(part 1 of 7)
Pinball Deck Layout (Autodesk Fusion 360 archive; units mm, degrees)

design "Pinball Deck Layout for Drawings" references "Pinball Flipper Full bushing"
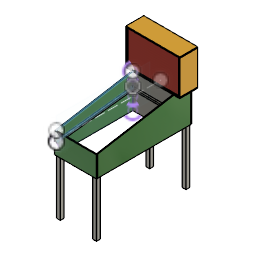
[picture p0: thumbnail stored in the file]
parameter "d345" = 2.4
sketch "Deck" plane through (0, 0, 0) normal (0, 0, 1) x axis (1, 0, 0)
  line L1 (500, 0) -> (0, 0)
  line L2 (500, 900) -> (500, 0)
  line L3 (0, 900) -> (500, 900)
  line L4 (0, 0) -> (0, 900)
  line L5 (250, 900) -> (250, 0)
  line L6 (265, 900) -> (265, 0)
  line L7 (235, 900) -> (235, 0)
  line L8 (475, 900) -> (475, 0)
  line L9 (25, 900) -> (25, 0)
  line L10 (500, 205) -> (0, 205)
  line L11 (500, 175) -> (0, 175)
  line L12 (175, 0) -> (175, 900)
  line L13 (325, 900) -> (325, 0)
  line L14 (187.7232, 167.6543) -> (175, 175)
  line L15 (189.6915, 175) -> (175, 175)
  line L16 (317.6007, 170.728) -> (325, 175)
  line L17 (333.544, 175) -> (325, 175)
  line L18 (317, 900) -> (317, 0)
  line L19 (183, 0) -> (183, 900)
  line L20 (500, 100) -> (0, 100)
  line L21 (500, 750) -> (500, 900)
  line L22 (500, 818.9103) -> (500, 750)
  line L23 (418.7386, 900) -> (350, 900)
  line L24 (0, 810) -> (500, 810)
  line L25 (0, 760) -> (500, 760)
  arc A1 centre (350, 750) radius 150 clockwise from (350, 900) to (500, 750)
  arc A2 centre (350, 750) radius 165 clockwise from (418.7386, 900) to (500, 818.7386)
  circle C1 centre (416.5624, 892.7435) radius 5
  circle C2 centre (416.5624, 892.7435) radius 2
  circle C3 centre (416.5624, 892.7435) radius 2
  circle C4 centre (416.5624, 892.7435) radius 5
  circle C5 centre (492.7435, 816.5624) radius 5
  circle C6 centre (492.7435, 816.5624) radius 2
  point P1 (0, 0)
  point P2 (0, 0)
  point P6 (0, 0)
  point P7 (250, 0)
  point P8 (250, 900)
  point P25 (175, 175)
  point P28 (325, 175)
  point P40 (350, 900)
  point P38 (350, 750)
  point P41 (350, 750)
  point P42 (500, 818.9103)
  point P43 (500, 818.7386)
  point P44 (418.7386, 900)
  coincident P1 P2
  horizontal L1
  perpendicular L1 L2
  perpendicular L2 L3
  coincident P1 P6
  perpendicular L1 L4
  midpoint L1 P7
  midpoint L3 P8
  horizontal L10
  horizontal L11
  horizontal L15
  coincident L11 P25
  coincident L12 P25
  horizontal L17
  coincident L11 P28
  coincident L13 P28
  horizontal L20
  perpendicular L3 L21
  coincident L3 P40
  coincident P38 P41
  coincident L21 P42
  coincident L2 P43
  coincident L3 P44
  tangent A1 L23
  concentric C1 C2
  concentric C3 C4
  concentric C5 C6
  dimension "d4" angle L14 L15 = 30
  dimension "d5" angle L16 L17 = 150
extrude "Extrude1" new body sketch "Deck" profile of L1 L2 L3 L4 L5 L6 L7 L8 L9 L10 L11 L12 L13 against normal blind 9
external_derived "ExternalDerived1"
move "Move1"
move "Move2"
move "Move3"
sketch "SCRATCH Sketch2" plane through (0, 0, 0) normal (0, 0, 1) x axis (1, 0, 0)
  line L1 (170.3253, 163.25) -> (183.8331, 184.2525)
  line L2 (165.6625, 180.1712) -> (177.0792, 173.7512)
  arc A1 centre (176.5753, 174.0753) radius 12.5 clockwise from (170.3253, 163.25) to (183.6642, 184.3709)
  point P2 (183.8331, 184.2525)
  point P4 (183.8331, 184.2525)
  point P3 (170.3253, 163.25)
  point P5 (170.3253, 163.25)
  point P9 (177.0792, 173.7512)
  point P10 (165.6625, 180.1712)
  coincident P2 P4
  coincident P3 P5
  midpoint L1 P9
  coincident A1 P10
move "Move4"
copy_paste_bodies "CopyPasteBodies1"
move "Move5"
move "Move6"
sketch "SCRATCH Sketch3" plane through (0, 0, 25.4) normal (0, 0, 1) x axis (-1, 0, 0)
  line L1 (-298.3283, -100.9362) -> (-297.8341, -101.7922)
  line L2 (-297.584, -100.5065) -> (-298.3283, -100.9362)
  line L3 (-297.0898, -101.3625) -> (-297.584, -100.5065)
  line L4 (-297.8341, -101.7922) -> (-297.0898, -101.3625)
  line L5 (-303.1949, -96.8044) -> (-299.6949, -102.8666)
  line L6 (-302.4506, -96.3746) -> (-303.1949, -96.8044)
  line L7 (-298.9506, -102.4368) -> (-302.4506, -96.3746)
  line L8 (-299.6949, -102.8666) -> (-298.9506, -102.4368)
  line L9 (-305.0971, -97.9026) -> (-302.5616, -102.2942)
  line L10 (-304.3528, -97.4729) -> (-305.0971, -97.9026)
  line L11 (-301.8173, -101.8644) -> (-304.3528, -97.4729)
  line L12 (-302.5616, -102.2942) -> (-301.8173, -101.8644)
  line L13 (-336.6609, -113.8819) -> (-335.4266, -116.0198)
  line L14 (-335.9166, -113.4522) -> (-336.6609, -113.8819)
  line L15 (-332.4094, -119.5268) -> (-335.9166, -113.4522)
  line L16 (-333.0876, -119.9183) -> (-332.4094, -119.5268)
  line L17 (-333.417, -119.3477) -> (-333.0876, -119.9183)
  curve K1 (-333.6687, -120.1628) -> (-333.417, -119.3477)
  curve K2 (-334.3039, -120.7529) -> (-333.6687, -120.1628)
  curve K3 (-335.4635, -121.0364) -> (-334.3039, -120.7529)
  curve K4 (-336.5842, -120.5946) -> (-335.4635, -121.0364)
  curve K5 (-337.4707, -119.5653) -> (-336.5842, -120.5946)
  curve K6 (-337.9295, -118.212) -> (-337.4707, -119.5653)
  curve K7 (-337.704, -116.9791) -> (-337.9295, -118.212)
  curve K8 (-336.9002, -116.1318) -> (-337.704, -116.9791)
  curve K9 (-336.1417, -115.9034) -> (-336.9002, -116.1318)
  curve K10 (-335.4266, -116.0198) -> (-336.1417, -115.9034)
  line L18 (-315.9189, -104.1506) -> (-314.5342, -106.549)
  line L19 (-315.1746, -103.7208) -> (-315.9189, -104.1506)
  line L20 (-312.6391, -108.1124) -> (-315.1746, -103.7208)
  line L21 (-313.309, -108.4992) -> (-312.6391, -108.1124)
  line L22 (-313.6695, -107.8747) -> (-313.309, -108.4992)
  curve K11
  curve K12 (-315.4616, -109.6841) -> (-314.6494, -109.4054)
  curve K13 (-316.176, -109.5975) -> (-315.4616, -109.6841)
  curve K14 (-316.7251, -109.1812) -> (-316.176, -109.5975)
  curve K15 (-317.1842, -108.4815) -> (-316.7251, -109.1812)
  line L23 (-318.7432, -105.7812) -> (-317.1842, -108.4815)
  line L24 (-317.9989, -105.3514) -> (-318.7432, -105.7812)
  line L25 (-316.4566, -108.0228) -> (-317.9989, -105.3514)
  curve K16 (-315.977, -108.6529) -> (-316.4566, -108.0228)
  curve K17 (-315.4612, -108.8348) -> (-315.977, -108.6529)
  curve K18 (-314.8647, -108.6695) -> (-315.4612, -108.8348)
  curve K19 (-314.2181, -107.8938) -> (-314.8647, -108.6695)
  curve K20 (-314.5342, -106.549) -> (-314.2181, -107.8938)
  line L26 (-329.0977, -111.7594) -> (-327.7106, -114.1619)
  line L27 (-328.3534, -111.3296) -> (-329.0977, -111.7594)
  line L28 (-324.8534, -117.3918) -> (-328.3534, -111.3296)
  line L29 (-325.5977, -117.8215) -> (-324.8534, -117.3918)
  line L30 (-326.8535, -115.6464) -> (-325.5977, -117.8215)
  curve K21 (-327.8199, -117.0094) -> (-326.8535, -115.6464)
  curve K22 (-328.7787, -117.3065) -> (-327.8199, -117.0094)
  curve K23 (-329.6003, -117.0724) -> (-328.7787, -117.3065)
  curve K24 (-330.3236, -116.1777) -> (-329.6003, -117.0724)
  line L31 (-331.9303, -113.3948) -> (-330.3236, -116.1777)
  line L32 (-331.186, -112.965) -> (-331.9303, -113.3948)
  line L33 (-329.5792, -115.748) -> (-331.186, -112.965)
  curve K25 (-328.8682, -116.4209) -> (-329.5792, -115.748)
  curve K26 (-328.037, -116.2801) -> (-328.8682, -116.4209)
  curve K27 (-327.5137, -115.7492) -> (-328.037, -116.2801)
  curve K28 (-327.3667, -115.044) -> (-327.5137, -115.7492)
  curve K29 (-327.7106, -114.1619) -> (-327.3667, -115.044)
  line L34 (-333.8118, -114.4811) -> (-331.2763, -118.8726)
  line L35 (-333.0675, -114.0513) -> (-333.8118, -114.4811)
  line L36 (-330.532, -118.4429) -> (-333.0675, -114.0513)
  line L37 (-331.2763, -118.8726) -> (-330.532, -118.4429)
  line L38 (-330.806, -119.6872) -> (-330.3118, -120.5432)
  line L39 (-330.0617, -119.2575) -> (-330.806, -119.6872)
  line L40 (-329.5675, -120.1135) -> (-330.0617, -119.2575)
  line L41 (-330.3118, -120.5432) -> (-329.5675, -120.1135)
  curve K30 (-325.4642, -110.9573) -> (-324.5473, -109.9096)
  curve K31 (-325.4308, -112.4762) -> (-325.4642, -110.9573)
  line L42 (-326.35, -112.7368) -> (-325.4308, -112.4762)
  curve K32 (-326.3126, -110.7055) -> (-326.35, -112.7368)
  curve K33 (-325.0098, -109.2614) -> (-326.3126, -110.7055)
  curve K34 (-323.1853, -108.7401) -> (-325.0098, -109.2614)
  curve K35 (-321.5835, -109.3563) -> (-323.1853, -108.7401)
  curve K36 (-320.3247, -110.7964) -> (-321.5835, -109.3563)
  curve K37 (-319.7328, -112.6573) -> (-320.3247, -110.7964)
  curve K38 (-320.1441, -114.3228) -> (-319.7328, -112.6573)
  curve K39 (-321.4028, -115.5375) -> (-320.1441, -114.3228)
  curve K40 (-323.2003, -115.9577) -> (-321.4028, -115.5375)
  curve K41 (-324.8166, -115.1541) -> (-323.2003, -115.9577)
  line L43 (-324.1342, -114.512) -> (-324.8166, -115.1541)
  curve K42 (-322.9659, -115.1221) -> (-324.1342, -114.512)
  curve K43 (-321.7826, -114.8415) -> (-322.9659, -115.1221)
  curve K44 (-320.8078, -113.8321) -> (-321.7826, -114.8415)
  curve K45 (-320.6675, -112.5519) -> (-320.8078, -113.8321)
  curve K46 (-321.1494, -111.278) -> (-320.6675, -112.5519)
  curve K47 (-322.1542, -110.058) -> (-321.1494, -111.278)
  curve K48 (-323.3529, -109.6005) -> (-322.1542, -110.058)
  curve K49 (-324.5473, -109.9096) -> (-323.3529, -109.6005)
  curve K50 (-310.472, -101.6619) -> (-312.3041, -101.9313)
  curve K51 (-308.9198, -103.0373) -> (-310.472, -101.6619)
  curve K52 (-308.5546, -105.236) -> (-308.9198, -103.0373)
  curve K53 (-309.6541, -106.5213) -> (-308.5546, -105.236)
  curve K54 (-311.4771, -106.7826) -> (-309.6541, -106.5213)
  curve K55 (-312.9985, -105.4749) -> (-311.4771, -106.7826)
  curve K56 (-313.5141, -103.9945) -> (-312.9985, -105.4749)
  curve K57 (-313.2096, -102.8124) -> (-313.5141, -103.9945)
  curve K58 (-312.3041, -101.9313) -> (-313.2096, -102.8124)
  curve K59 (-308.2724, -100.7779) -> (-307.6957, -100.0866)
  curve K60 (-308.1671, -101.8199) -> (-308.2724, -100.7779)
  line L44 (-308.954, -102.1473) -> (-308.1671, -101.8199)
  curve K61 (-309.0239, -100.6081) -> (-308.954, -102.1473)
  curve K62 (-308.0573, -99.4794) -> (-309.0239, -100.6081)
  curve K63 (-306.2677, -99.2318) -> (-308.0573, -99.4794)
  curve K64 (-304.7445, -100.6047) -> (-306.2677, -99.2318)
  curve K65 (-304.2616, -101.9855) -> (-304.7445, -100.6047)
  curve K66 (-304.5171, -103.1999) -> (-304.2616, -101.9855)
  curve K67 (-305.4114, -104.0718) -> (-304.5171, -103.1999)
  curve K68 (-306.7905, -104.3856) -> (-305.4114, -104.0718)
  curve K69 (-307.9669, -103.6947) -> (-306.7905, -104.3856)
  line L45 (-307.3077, -103.1652) -> (-307.9669, -103.6947)
  curve K70 (-306.5573, -103.6197) -> (-307.3077, -103.1652)
  curve K71 (-305.7937, -103.4765) -> (-306.5573, -103.6197)
  curve K72 (-305.1126, -102.5457) -> (-305.7937, -103.4765)
  curve K73 (-305.4976, -101.0671) -> (-305.1126, -102.5457)
  curve K74 (-306.5792, -99.9768) -> (-305.4976, -101.0671)
  curve K75 (-307.6957, -100.0866) -> (-306.5792, -99.9768)
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  point P165 (-326.7759, -128.0741)
  point P171 (-326.7759, -128.0741)
  point P169 (-338.2107, -105.8748)
  point P172 (-338.2107, -105.8748)
  point P173 (-332.5441, -116.6768)
  coincident P165 P171
  coincident P169 P172
  midpoint L34 P173
move "Move7"
move "Move8"
move "Move9"
sketch "Bottom Runways" plane through (0, 0, 0) normal (0, 0, 1) x axis (1, 0, 0)
  line L1 (35, 200) -> (235, 100)
  line L2 (382.2216, 133.6108) -> (309.7214, 97.3607)
  line L3 (265, 100) -> (265, 84.3827)
  line L4 (235, 75) -> (235, 100)
  line L5 (30, 177.5) -> (215, 85)
  line L6 (187.1443, 36.0721) -> (235, 60)
  line L7 (235, 60) -> (235, 75)
  line L8 (215, 70) -> (215, 85)
  line L9 (205, 45) -> (201.3653, 45.918)
  line L10 (197.2105, 61.1053) -> (215, 70)
  line L11 (95, 10) -> (170.0223, 47.5111)
  line L12 (475.0759, 10) -> (475.0759, 180)
  line L13 (500, 55) -> (500, 55)
  line L14 (500, 35) -> (500, 55)
  line L15 (500, 60) -> (500, 55)
  line L16 (465, 101) -> (475.0759, 96.9696)
  line L17 (465, 20) -> (465, 70)
  line L18 (436.9865, 55.459) -> (436.9865, 85.2054)
  line L19 (442.002, 24.3778) -> (442.002, 10)
  line L20 (437.4865, 56.1294) -> (437.4865, 75.0054)
  line L21 (442.489, 73.0044) -> (464.5, 64.2)
  line L22 (441.9865, 73.2054) -> (442.489, 73.0044)
  line L23 (464.5, 23) -> (455.75, 23)
  line L24 (455.75, 23) -> (455.75, 44.291)
  line L25 (464.5, 23) -> (464.5, 64.2)
  line L26 (437.4865, 85.0054) -> (437.4865, 75.0054)
  line L27 (441.9885, 83.2046) -> (441.9908, 73.2037)
  line L28 (382.2216, 106.6108) -> (387.2417, 104.6487)
  line L29 (437.4865, 121.6401) -> (437.4865, 85.0054)
  line L30 (441.9885, 121.6401) -> (441.9885, 83.2046)
  line L31 (437.4865, 121.6401) -> (441.9885, 121.6401)
  line L32 (436.9865, 133.2054) -> (436.9865, 112.2054)
  line L33 (436.9865, 133.2054) -> (441.4885, 133.2054)
  line L34 (442.4885, 133.2054) -> (441.4885, 133.2054)
  line L35 (442.4885, 110.0046) -> (442.4885, 133.2054)
  line L36 (442.4885, 110.0046) -> (465, 101)
  line L37 (438.1128, 99.7549) -> (441.9885, 98.2046)
  line L38 (437.4865, 100.0054) -> (438.1128, 99.7549)
  line L39 (437.4865, 75.0054) -> (441.9865, 73.2054)
  line L40 (465, 10) -> (465, 20)
  line L41 (475.0759, 180) -> (475.0152, 200)
  line L42 (265, 84.3827) -> (265, 86.0924)
  line L43 (265, 48) -> (265, 84.5)
  line L44 (265, 48) -> (265.011, 48.0055)
  line L45 (189, 10) -> (264.7, 47.85)
  line L46 (0.189, -124.2988) -> (0.189, 200)
  line L47 (500, 0) -> (500, 10)
  line L48 (189, 0) -> (264.7, 0)
  line L49 (189, 10) -> (189, 0)
  line L50 (188.3292, 10) -> (197.8101, 14.7405)
  line L51 (188.3292, 10) -> (30, 10)
  line L52 (188.3292, 0) -> (188.3292, 10)
  line L53 (30, 0) -> (188.3292, 0)
  line L54 (305, 26.7) -> (310.3, 26.7)
  line L55 (310.3, 32.3) -> (305, 32.3)
  line L56 (304.7, 32) -> (304.7, 47.85)
  line L57 (305, 0) -> (305, 10)
  line L58 (304.7, 0) -> (304.7, 10)
  line L59 (310, 27) -> (310, 32)
  line L60 (310, 32) -> (304.7, 32)
  line L61 (305, 10) -> (305, 26.7)
  line L62 (304.7, 27) -> (310, 27)
  line L63 (304.7, 10) -> (304.7, 27)
  line L64 (305, 32.3) -> (305, 48)
  line L65 (310.3, 26.7) -> (310.3, 32.3)
  line L66 (304.7076, 119.8538) -> (265, 100)
  line L67 (465, 200) -> (305.0076, 120.0038)
  line L68 (304.705, 95.4133) -> (269.0857, 81.586)
  line L69 (309.7214, 97.3607) -> (305.005, 95.5298)
  line L70 (304.7021, 67.8511) -> (265.011, 48.0055)
  line L71 (382.2216, 106.6108) -> (305.0021, 68.0011)
  line L72 (310.3, 112.3) -> (305, 112.3)
  line L73 (310, 112) -> (304.7, 112)
  line L74 (310, 107) -> (310, 112)
  line L75 (310.3, 106.7) -> (310.3, 112.3)
  line L76 (304.7, 107) -> (310, 107)
  line L77 (305, 106.7) -> (310.3, 106.7)
  line L78 (305.0062, 106.7) -> (305, 48)
  line L79 (305.0076, 120.0038) -> (305.0068, 112.3)
  line L80 (265, 48) -> (264.7, 47.85)
  line L81 (265, 0) -> (264.7, 0)
  line L82 (304.7, 10) -> (189, 10)
  line L83 (500, 10) -> (305, 10)
  line L84 (305, 0) -> (500, 0)
  line L85 (265, 0) -> (304.7, 0)
  line L86 (382.2216, 96.6108) -> (305.0021, 58.0011)
  line L87 (382.2216, 96.6108) -> (387.2417, 94.6487)
  line L88 (305.0011, 58.0005) -> (305.0021, 58.0011)
  line L89 (305.0011, 58.0005) -> (305.0021, 58.0011)
  line L90 (209, 10) -> (304.7011, 57.8505)
  line L91 (304.7062, 107) -> (304.7, 47.85)
  line L92 (304.7076, 119.8538) -> (304.7067, 112)
  line L93 (455.25, 30) -> (455.25, 23)
  line L94 (455.25, 10) -> (455.25, 23)
  line L95 (426.9865, 59.7353) -> (436.9865, 59.7353)
  line L96 (452.1681, 30) -> (455.25, 30)
  line L97 (441.9908, 56.2022) -> (441.9908, 73.2037)
  line L98 (465, 200) -> (0.189, 200)
  line L99 (30, 200) -> (35, 200)
  line L100 (30, 0) -> (30, 200)
  line L101 (470.038, 72.2189) -> (475.0759, 72.2189)
  line L102 (414.4865, 128) -> (414.4865, 95.0841)
  line L103 (414.4865, 73) -> (414.4865, 95.0841)
  line L104 (409.9865, 128) -> (409.9865, 95.0841)
  line L105 (409.9865, 73) -> (409.9865, 95.0841)
  line L106 (414.9865, 128) -> (414.9865, 120.8043)
  line L107 (414.4865, 141.8043) -> (409.9865, 141.8043)
  line L108 (414.9865, 141.8043) -> (414.4865, 141.8043)
  line L109 (414.9865, 141.8043) -> (414.9865, 128.0189)
  line L110 (409.4865, 141.8043) -> (409.4865, 128)
  line L111 (409.4865, 141.8043) -> (409.9865, 141.8043)
  line L112 (414.9865, 120.8043) -> (436.9865, 112.2054)
  line L113 (382.2216, 133.6108) -> (409.4865, 122.9541)
  line L114 (414.4865, 73) -> (409.9865, 73)
  line L115 (409.4865, 61) -> (409.4865, 95.0841)
  line L116 (414.9865, 61) -> (409.4865, 61)
  line L117 (414.9865, 61) -> (414.9865, 93.8043)
  line L118 (409.4865, 95.9541) -> (409.4865, 95.0841)
  line L119 (409.4865, 128) -> (409.4865, 122.9541)
  line L120 (414.9865, 93.8043) -> (436.9865, 85.2054)
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  point P16 (189, 10)
  point P17 (95, 10)
  point P20 (170.0223, 47.5111)
  point P23 (205, 45)
  point P28 (197.2105, 61.1053)
  point P26 (185.8525, 49.8361)
  point P27 (185.8525, 49.8361)
  point P33 (475.0759, 10)
  point P48 (441.9865, 73.2054)
  point P40 (440, 40)
  point P53 (440, 40)
  point P70 (441.9908, 73.2037)
  point P82 (437.4865, 100.0054)
  point P83 (441.9885, 98.2046)
  point P47 (442.002, 10)
  point P85 (465, 10)
  point P86 (475.0759, 72.2189)
  point P87 (475.0759, 96.9696)
  point P88 (265, 86.0924)
  point P90 (264.7, 47.85)
  point P91 (265, 84.5)
  point P30 (0.189, -124.2988)
  point P92 (0.189, -124.2988)
  point P32 (500, 0)
  point P93 (500, 0)
  point P102 (304.7, 27)
  point P114 (305.0076, 120.0038)
  point P116 (304.705, 95.4133)
  point P117 (305.005, 95.5298)
  point P118 (304.7021, 67.8511)
  point P119 (305.0021, 68.0011)
  point P128 (305.0068, 112.3)
  point P129 (305.0062, 106.7)
  point P133 (305.0011, 58.0005)
  point P134 (209, 10)
  point P135 (304.7011, 57.8505)
  point P136 (304.7062, 107)
  point P137 (304.7067, 112)
  point P138 (440, 40)
  point P140 (455.25, 10)
  point P141 (436.9865, 59.7353)
  point P193 (35, 200)
  point P195 (475.0152, 200)
  point P198 (30, 177.5)
  point P199 (30, 10)
  point P219 (409.4865, 122.9541)
  point P222 (409.4865, 95.9541)
  point P227 (409.9865, 95.7586)
  point P228 (414.4865, 93.9998)
  point P229 (409.9865, 120.7586)
  point P230 (414.4865, 118.9998)
  point P22 (185.8525, 49.8361)
  point P243 (185.8525, 49.8361)
  point P21 (185.8525, 49.8361)
  point P244 (185.8525, 49.8361)
  point P255 (40, 420)
  point P279 (40, 420)
  point P331 (290, 750)
  point P336 (290, 750)
  point P355 (290, 750)
  point P350 (290, 847)
  point P357 (290, 847)
  point P356 (290, 750)
  point P389 (103.6396, 808.3604)
  point P392 (103.6396, 808.3604)
  point P466 (437.4865, 85.0089)
  point P330 (384.1244, 660.5936)
  point P338 (381.2382, 661.4119)
  point P387 (40, 872)
  point P474 (441.9885, 96.2046)
  parallel L2 L6
  parallel L4 L7
  vertical L8
  coincident P16 L51
  coincident P17 L51
  coincident P20 L10
  coincident L6 P23
  coincident P28 L10
  coincident P26 P27
  collinear L10 L11
  coincident P33 L51
  perpendicular L12 L51
  perpendicular L17 L51
  vertical L18
  vertical L25
  coincident P48 L21
  vertical L20
  coincident P40 P53
  perpendicular L23 L25
  parallel L20 L26
  coincident L22 P70
  parallel L16 L36
  parallel L28 L120
  parallel L26 L29
  perpendicular L29 L31
  parallel L26 L32
  parallel L33 L34
  perpendicular L34 L35
  parallel L37 L38
  coincident L29 P82
  coincident L30 P83
  parallel L22 L39
  coincident P47 L51
  perpendicular L19 L51
  coincident P85 L51
  perpendicular L40 L51
  coincident L12 P86
  coincident L12 P87
  coincident L3 P88
  perpendicular L42 L51
  coincident P90 L44
  collinear L44 L45
  coincident L3 P91
  coincident P30 P92
  perpendicular L46 L51
  coincident P32 P93
  perpendicular L47 L51
  perpendicular L47 L84
  collinear L51 L82
  perpendicular L48 L52
  perpendicular L60 L64
  perpendicular L59 L60
  coincident P102 L56
  perpendicular L56 L62
  collinear L56 L63
  collinear L61 L64
  perpendicular L55 L64
  perpendicular L55 L65
  perpendicular L54 L61
  coincident P114 L66
  parallel L78 L91
  collinear L66 L67
  coincident P116 L91
  coincident P117 L78
  collinear L68 L69
  coincident P118 L91
  coincident P119 L78
  collinear L70 L71
  perpendicular L73 L74
  perpendicular L72 L75
  coincident L72 P128
  collinear L78 L79
  coincident L77 P129
  parallel L70 L80
  collinear L82 L83
  collinear L84 L85
  parallel L86 L88
  coincident L78 P133
  parallel L86 L89
  coincident L82 P134
  coincident P135 L91
  collinear L89 L90
  coincident L76 P136
  coincident L73 P137
  collinear L91 L92
  coincident P53 P138
  coincident L83 P140
  perpendicular L83 L94
  coincident L18 P141
  perpendicular L93 L96
  vertical L97
  coincident P193 L98
  collinear L98 L99
  coincident L98 P195
  perpendicular L53 L100
  coincident L100 P198
  coincident L100 P199
  perpendicular L12 L101
  parallel L107 L108
  perpendicular L108 L109
  parallel L110 L118
  perpendicular L110 L111
  collinear L112 L113
  coincident P219 L118
  perpendicular L103 L114
  parallel L105 L115
  perpendicular L115 L116
  perpendicular L116 L117
  coincident P222 L120
  collinear L118 L119
  coincident L104 P227
  coincident L103 P228
  coincident L104 P229
  coincident L102 P230
  coincident P22 P243
  coincident P21 P244
  coincident P255 P279
  coincident P331 P336
  coincident P331 P355
  coincident P350 P357
  coincident P336 P356
  coincident P389 P392
  coincident L29 P466
  dimension "d8" radius = 3
  dimension "d40" radius = 16
  dimension "d225" diameter = 7.6
  dimension "d290" diameter = 8
  dimension "d293" diameter = 15
  dimension "d363" radius = 2
  dimension "d364" radius = 1.5
  dimension "d494" diameter = 18
  dimension "d495" diameter = 4.5
  dimension "d497" diameter = 8
  dimension "d498" diameter = 8
  dimension "d499" diameter = 4.5
  dimension "d500" diameter = 4.5
  dimension "d510" diameter = 100
  dimension "d514" diameter = 8
  dimension "d515" diameter = 4.5
  dimension "d518" diameter = 8
  dimension "d519" diameter = 4.5
  dimension "d524" diameter = 8
  dimension "d525" diameter = 4.5
  dimension "d552" diameter = 18
  dimension "d553" diameter = 24
  dimension "d557" radius = 60
  dimension "d564" diameter = 8
  dimension "d565" diameter = 8
  dimension "d566" diameter = 3.8
  dimension "d567" diameter = 3.8
  dimension "d591" diameter = 8
  dimension "d592" diameter = 8
  dimension "d593" diameter = 3.8
  dimension "d594" diameter = 3.8
  dimension "d601" distance P330 P338 = 3
  dimension "d612" radius = 50
  dimension "d613" radius = 52
  dimension "d614" radius = 80
  dimension "d616" diameter = 4
  dimension "d617" diameter = 12
  dimension "d655" distance P387 P389 = 90
  dimension "d687" diameter = 8
  dimension "d688" diameter = 4.5
  dimension "d689" diameter = 8
  dimension "d690" diameter = 4.5
  dimension "d691" diameter = 8
  dimension "d692" diameter = 4.5
  dimension "d693" diameter = 8
  dimension "d694" diameter = 4.5
  dimension "d695" diameter = 8
  dimension "d696" diameter = 4.5
  dimension "d746" diameter = 8
  dimension "d747" diameter = 4.5
  dimension "d777" diameter = 4.5
  dimension "d778" diameter = 8
  dimension "d779" diameter = 12
  dimension "d780" radius = 30
  dimension "d866" radius = 10
  dimension "d888" diameter = 4.5
  dimension "d889" diameter = 8
  dimension "d890" radius = 80
  dimension "d916" diameter = 8.5
  dimension "d918" diameter = 8.5
  dimension "d924" diameter = 15
  dimension "d1303" diameter = 2.7
  dimension "d1311" distance P83 P474 = 2
sketch "Reload Plunger" plane through (0, 0, 0) normal (0, 0, 1) x axis (1, 0, 0)
  line L1 (107.246, 52.5518) -> (74.0474, 36.2161)
  line L2 (111.2277, 44.4598) -> (130.0702, 53.7314)
  line L3 (113.0223, 45.3428) -> (130.0702, 53.7314)
  line L4 (109.0487, 53.4181) -> (84.7472, 41.481)
  line L5 (111.2277, 44.4598) -> (130.0702, 53.7314)
  line L6 (74.0474, 36.2161) -> (85.5333, 12.8737)
  line L7 (130.9104, 45.2288) -> (127.3784, 52.4069)
  line L8 (116.5543, 38.1647) -> (113.0223, 45.3428)
  line L9 (130.0702, 53.7314) -> (133.6022, 46.5533)
  line L10 (128.2187, 43.9043) -> (124.6866, 51.0824)
  line L11 (116.5543, 38.1647) -> (133.6022, 46.5533)
  line L12 (130.0702, 53.7314) -> (133.6022, 46.5533)
  line L13 (118.7318, 29.2095) -> (107.246, 52.5518)
  line L14 (130.9104, 45.2288) -> (127.3784, 52.4069)
  line L15 (96.2312, 18.1378) -> (120.5273, 30.0906)
  line L16 (107.246, 52.5518) -> (74.0474, 36.2161)
  line L17 (84.7472, 41.481) -> (96.2312, 18.1378)
  line L18 (85.5333, 12.8737) -> (118.7318, 29.2095)
  line L19 (133.6022, 46.5533) -> (114.7598, 37.2817)
  line L20 (128.2187, 43.9043) -> (124.6866, 51.0824)
  line L21 (114.7598, 37.2817) -> (111.2277, 44.4598)
  line L22 (94.4613, 19.4702) -> (117.83, 30.8678)
  line L23 (108.1858, 50.6413) -> (74.9304, 34.4215)
  line L24 (108.1858, 50.6413) -> (84.8172, 39.2436)
  line L25 (108.1858, 50.6413) -> (74.9304, 34.4215)
  line L26 (108.1858, 50.6413) -> (74.9304, 34.4215)
  line L27 (85.7923, 24.6991) -> (91.2583, 27.3626)
  line L28 (108.1858, 50.6413) -> (117.83, 30.8678)
  line L29 (117.83, 30.8678) -> (84.5746, 14.6481)
  line L30 (117.83, 30.8678) -> (84.5746, 14.6481)
  line L31 (117.83, 30.8678) -> (84.5746, 14.6481)
  line L32 (110.4742, 33.3995) -> (105.2009, 30.8342)
  line L33 (105.6521, 43.2862) -> (100.3841, 40.7101)
  line L34 (88.992, 31.8227) -> (83.6843, 29.2374)
  line L35 (74.9304, 34.4215) -> (84.5746, 14.6481)
  line L36 (109.1591, 36.0958) -> (103.891, 33.5197)
  line L37 (108.1858, 50.6413) -> (117.83, 30.8678)
  line L38 (108.1858, 50.6413) -> (117.83, 30.8678)
  line L39 (74.9304, 34.4215) -> (84.5746, 14.6481)
  line L40 (106.9672, 40.5898) -> (101.6939, 38.0245)
  line L41 (92.4997, 24.6327) -> (87.1069, 22.0025)
  line L42 (74.9304, 34.4215) -> (84.5746, 14.6481)
  line L43 (87.6776, 34.5194) -> (82.2849, 31.8892)
  line L44 (85.7923, 24.6991) -> (91.1137, 27.2922)
  line L45 (84.8172, 39.2436) -> (94.4613, 19.4702)
  line L46 (92.4997, 24.6327) -> (87.1069, 22.0025)
  line L47 (117.83, 30.8678) -> (108.1858, 50.6413)
  line L48 (74.9304, 34.4215) -> (74.0474, 36.2161)
  arc A1 centre (104.4253, 32.1181) radius 1.5 clockwise from (105.2015, 30.8345) to (103.8917, 33.52)
  arc A2 centre (100.9183, 39.3084) radius 1.5 clockwise from (101.6945, 38.0249) to (100.3847, 40.7103)
  arc A3 centre (109.818, 34.7483) radius 1.5 clockwise from (109.1591, 36.0958) to (110.4742, 33.3995)
  arc A4 centre (82.9424, 30.541) radius 1.5 clockwise from (83.6843, 29.2374) to (82.2849, 31.8892)
  circle C1 centre (103.6147, 40.6236) radius 1.5
  arc A5 centre (91.8421, 25.9809) radius 1.5 clockwise from (91.2583, 27.3626) to (92.4997, 24.6327)
  circle C2 centre (103.6147, 40.6236) radius 1.5
  arc A6 centre (106.3111, 41.9387) radius 1.5 clockwise from (105.6521, 43.2862) to (106.9672, 40.5898)
  circle C3 centre (111.1442, 33.1699) radius 2
  circle C4 centre (107.1216, 33.4332) radius 1.5
  arc A7 centre (100.9183, 39.3084) radius 1.5 clockwise from (101.6945, 38.0249) to (100.3847, 40.7103)
  arc A8 centre (86.4494, 23.3507) radius 1.5 clockwise from (87.1069, 22.0025) to (85.7923, 24.6991)
  arc A9 centre (82.9424, 30.541) radius 1.5 clockwise from (83.6845, 29.2374) to (82.2849, 31.8892)
  arc A10 centre (91.8421, 25.9809) radius 1.5 clockwise from (91.1137, 27.2922) to (92.4997, 24.6327)
  arc A11 centre (86.4494, 23.3507) radius 1.5 clockwise from (87.1069, 22.0025) to (85.7923, 24.6991)
  arc A12 centre (86.4494, 23.3507) radius 1.5 clockwise from (87.1069, 22.0025) to (85.7923, 24.6991)
  circle C5 centre (107.1216, 33.4332) radius 1.5
  circle C6 centre (89.1458, 24.6658) radius 1.5
  arc A13 centre (104.4253, 32.1181) radius 1.5 clockwise from (105.2015, 30.8345) to (103.8917, 33.52)
  circle C7 centre (91.9524, 37.1607) radius 2
  arc A14 centre (88.3352, 33.1712) radius 1.5 clockwise from (87.6776, 34.5194) to (88.992, 31.8227)
  circle C8 centre (89.1458, 24.6658) radius 1.5
  circle C9 centre (89.1458, 24.6658) radius 1.5
  arc A15 centre (82.9424, 30.541) radius 1.5 clockwise from (83.6845, 29.2374) to (82.2849, 31.8892)
  circle C10 centre (85.6388, 31.8561) radius 1.5
  circle C11 centre (107.1216, 33.4332) radius 1.5
  arc A16 centre (104.4253, 32.1181) radius 1.5 clockwise from (105.2009, 30.8342) to (103.891, 33.5197)
  circle C12 centre (103.6147, 40.6236) radius 1.5
  circle C13 centre (85.6388, 31.8561) radius 1.5
  arc A17 centre (100.9183, 39.3084) radius 1.5 clockwise from (101.6939, 38.0245) to (100.3841, 40.7101)
  circle C14 centre (85.6388, 31.8561) radius 1.5
  circle C15 centre (111.1442, 33.1699) radius 3.25
  circle C16 centre (107.1216, 33.4332) radius 3.25
  circle C17 centre (103.6147, 40.6236) radius 3.25
  circle C18 centre (91.9524, 37.1607) radius 3.25
  circle C19 centre (89.1458, 24.6658) radius 3.25
  circle C20 centre (85.6388, 31.8561) radius 3.25
  point P11 (133.6022, 46.5533)
  point P33 (133.6022, 46.5533)
  point P12 (130.0702, 53.7314)
  point P28 (130.0702, 53.7314)
  point P30 (133.6022, 46.5533)
  point P3 (127.3784, 52.4069)
  point P15 (127.3784, 52.4069)
  point P2 (130.9104, 45.2288)
  point P10 (130.9104, 45.2288)
  point P29 (124.6866, 51.0824)
  point P35 (124.6866, 51.0824)
  point P34 (128.2187, 43.9043)
  point P36 (128.2187, 43.9043)
  point P27 (84.7472, 41.481)
  point P40 (94.4613, 19.4702)
  point P41 (94.4613, 19.4702)
  point P45 (94.4613, 19.4702)
  point P22 (74.0474, 36.2161)
  point P136 (74.9304, 34.4215)
  coincident P11 P33
  coincident P12 P28
  perpendicular L3 L12
  perpendicular L5 L8
  coincident P30 P33
  perpendicular L8 L11
  coincident P3 P15
  coincident P2 P10
  coincident P29 P35
  coincident P34 P36
  coincident P27 L16
  perpendicular L15 L17
  coincident P40 P41
  perpendicular L24 L45
  perpendicular L24 L47
  coincident P41 P45
  perpendicular L22 L45
  perpendicular L1 L48
  concentric C3 C15
  dimension "d9" distance P22 P136 = 2
  dimension "d925" diameter C3 = 4
  dimension "d926" diameter C7 = 4
sketch "Reload Flipper" plane through (0, 0, 0) normal (0, 0, 1) x axis (1, 0, 0)
  line L1 (189.2611, 51.9302) -> (189.2253, 51.9883)
  line L2 (182.2905, 34.7509) -> (182.74, 19.3347)
  line L3 (184.5475, 75.9042) -> (188.377, 65.1291)
  line L4 (190.2871, 34.984) -> (190.8175, 16.7929)
  line L5 (193.9662, 36.6294) -> (185.8525, 49.8361)
  line L6 (190.2939, 34.7513) -> (190.1715, 34.95)
  line L7 (170.4136, 70.881) -> (174.243, 60.106)
  circle C1 centre (185.8525, 49.8361) radius 12.5
  arc A1 centre (185.7387, 19.4222) radius 3 clockwise from (185.7275, 16.4222) to (182.74, 19.3347)
  arc A2 centre (185.8525, 49.8361) radius 33.4141 clockwise from (190.8175, 16.7929) to (185.7275, 16.4222)
  circle C2 centre (185.8525, 49.8361) radius 5.375
  arc A3 centre (185.8525, 49.8361) radius 15.5 clockwise from (182.2905, 34.7509) to (174.1149, 59.9593)
  circle C3 centre (177.4806, 73.3926) radius 1.85
  arc A4 centre (177.4806, 73.3926) radius 7.5 clockwise from (170.4136, 70.881) to (184.5475, 75.9042)
  arc A5 centre (185.8525, 49.8361) radius 15.5 clockwise from (197.0999, 39.1709) to (190.1715, 34.95)
  arc A6 centre (185.8525, 49.8361) radius 15.5 clockwise from (174.1149, 59.9593) to (174.243, 60.106)
  arc A7 centre (185.8525, 49.8361) radius 15.5 clockwise from (188.377, 65.1291) to (197.0999, 39.1709)
  point P9 (197.0999, 39.1709)
  point P12 (174.1149, 59.9593)
  point P8 (185.8525, 49.8361)
  point P20 (185.8525, 49.8361)
  point P2 (185.8525, 49.8361)
  point P26 (185.8525, 49.8361)
  point P25 (185.8525, 49.8361)
  point P3 (190.2871, 34.984)
  point P23 (190.2939, 34.7513)
  point P31 (193.9662, 36.6294)
  point P22 (185.8525, 49.8361)
  point P27 (185.8525, 49.8361)
  concentric C2 A7
  coincident P9 L1
  coincident P12 A7
  concentric A3 A7
  concentric C3 A4
  coincident P8 P20
  concentric C1 C2
  coincident P2 P26
  coincident P2 P25
  coincident P3 A5
  coincident P23 L4
  coincident P31 A5
  tangent A1 L2
  tangent A1 A2
  coincident P22 P27
  dimension "d365" diameter C2 = 10.75
  dimension "d366" diameter A7 = 31
  dimension "d367" diameter C3 = 3.7
  dimension "d368" diameter A4 = 15
  dimension "d369" diameter C1 = 25
  dimension "d370" radius A1 = 3
sketch "reload coupling" plane through (0, 0, 0) normal (0, 0, 1) x axis (1, 0, 0)
  line L1 (182.9196, 67.3244) -> (131.992, 42.4436)
  line L2 (177.176, 81.1418) -> (125.3353, 55.9165)
  line L3 (123.51, 50.5264) -> (126.6606, 44.2444)
  line L4 (134.7248, 43.7787) -> (128.4353, 40.7059)
  line L5 (168.7441, 60.399) -> (165.2756, 67.4985)
  line L6 (162.1861, 73.8478) -> (165.2756, 67.4985)
  line L7 (165.9515, 59.4512) -> (162.5974, 66.1594)
  line L8 (159.4249, 72.5042) -> (162.5974, 66.1594)
  line L9 (166.1158, 59.1149) -> (165.9515, 59.4512)
  line L10 (136.3196, 61.2613) -> (142.8863, 47.766)
  line L11 (145.5841, 49.0787) -> (142.8863, 47.766)
  line L12 (139.0173, 62.5741) -> (145.5841, 49.0787)
  line L13 (124.4038, 50.9748) -> (123.51, 50.5264)
  circle C1 centre (130.184, 49.9541) radius 1.9
  arc A1 centre (130.2361, 46.0376) radius 4 clockwise from (131.992, 42.4436) to (126.6606, 44.2444)
  arc A2 centre (127.0855, 52.3197) radius 4 clockwise from (123.51, 50.5264) to (125.3353, 55.9165)
  circle C2 centre (179.5655, 74.0326) radius 1.9
  arc A3 centre (179.5655, 74.0326) radius 7.5 clockwise from (177.176, 81.1418) to (182.9196, 67.3244)
  point P6 (134.7248, 43.7787)
  point P4 (128.4353, 40.7059)
  point P16 (168.7441, 60.399)
  point P17 (162.1861, 73.8478)
  point P2 (179.5655, 74.0326)
  point P20 (179.5655, 74.0326)
  point P21 (166.1158, 59.1149)
  point P22 (159.4249, 72.5042)
  point P23 (142.8863, 47.766)
  point P24 (136.3196, 61.2613)
  point P26 (139.0173, 62.5741)
  point P12 (123.51, 50.5264)
  point P27 (124.4038, 50.9748)
  coincident L1 P6
  coincident P4 L1
  coincident P4 L3
  tangent L1 A1
  tangent L3 A1
  tangent L2 A2
  tangent L3 A2
  coincident L1 P16
  perpendicular L1 L5
  coincident L2 P17
  perpendicular L2 L6
  coincident P2 P20
  coincident L1 P21
  perpendicular L1 L9
  coincident L2 P22
  coincident L1 P23
  coincident L2 P24
  perpendicular L2 L10
  perpendicular L10 L11
  coincident L2 P26
  perpendicular L2 L12
  perpendicular L3 L13
  dimension "d41" distance P4 P6 = 7
  dimension "d42" diameter C1 = 3.8
  dimension "d43" radius A1 = 4
  dimension "d44" radius A2 = 4
  dimension "d347" distance P12 P27 = 1
sketch "Launch Plunger" plane through (0, 0, 0) normal (0, 0, 1) x axis (1, 0, 0)
  line L1 (500, 0) -> (0, 0)
  line L2 (487.5, -9) -> (487.5, 0)
  line L3 (502.5, -9) -> (487.5, -9)
  line L4 (502.5, -12.5) -> (502.5, -9)
  line L5 (472.5, -12.5) -> (502.5, -12.5)
  line L6 (472.5, -9) -> (472.5, -12.5)
  line L7 (487.5, -9) -> (472.5, -9)
  line L8 (495.5, -12.5) -> (487.5, -12.5)
  line L9 (495.5, -28.5) -> (495.5, -12.5)
  line L10 (487.5, -12.5) -> (479.5, -12.5)
  line L11 (479.5, -28.5) -> (479.5, -12.5)
  line L12 (479.5, -28.5) -> (495.5, -28.5)
  line L13 (487.5, -41.5) -> (487.5, -28.5)
  line L14 (494, 9) -> (494, -9)
  line L15 (481, 9) -> (481, -9)
  line L16 (494, 9) -> (481, 9)
  line L17 (481.5, 53) -> (481.5, 9)
  line L18 (493.5, 53) -> (493.5, 9)
  line L19 (493.5, 53) -> (481.5, 53)
  line L20 (479.125, 72) -> (495.875, 72)
  line L21 (493.5, 53) -> (495.875, 72)
  line L22 (481.5, 53) -> (479.125, 72)
  line L23 (493.5, 27) -> (481.5, 27)
  line L24 (479.125, 46) -> (495.875, 46)
  line L25 (481.5, 27) -> (479.125, 46)
  line L26 (493.5, 27) -> (495.875, 46)
  circle C1 centre (487.5, -41.5) radius 13
  point P4 (487.5, 0)
  point P10 (487.5, -12.5)
  point P11 (495.5, -12.5)
  point P17 (487.5, -28.5)
  point P18 (487.5, -41.5)
  point P19 (487.5, -41.5)
  point P26 (481.5, 9)
  point P27 (481.5, 53)
  point P28 (493.5, 9)
  point P29 (493.5, 53)
  coincident L1 P4
  perpendicular L1 L2
  perpendicular L2 L3
  perpendicular L3 L4
  perpendicular L4 L5
  perpendicular L3 L6
  perpendicular L2 L7
  midpoint L5 P10
  coincident L5 P11
  perpendicular L8 L9
  perpendicular L11 L12
  midpoint L12 P17
  perpendicular L12 L13
  coincident P18 P19
  coincident P17 C1
  perpendicular L14 L16
  perpendicular L18 L19
  dimension "d51" distance P17 P18 = 13
  dimension "d55" distance P26 P27 = 44
  dimension "d56" distance P28 P29 = 44
sketch "Launch_reload_Plunger" plane through (0, 0, 0) normal (0, 0, 1) x axis (1, 0, 0)
  line L1 (332.4666, 60.0013) -> (332.3898, 38.0014)
  line L2 (384.4666, 44.9827) -> (384.4666, 52.9827)
  line L3 (343.4665, 59.9629) -> (343.3898, 37.963)
  line L4 (371.4666, 44.9827) -> (390.4666, 44.9827)
  line L5 (369.4666, 52.9827) -> (390.4666, 52.9827)
  line L6 (344.3915, 62.0013) -> (344.3895, 35.9861)
  line L7 (369.4666, 35.9861) -> (369.4666, 62.0013)
  line L8 (363.9352, 51.3914) -> (358.071, 51.4179)
  line L9 (369.3896, 37.8723) -> (369.4664, 59.8721)
  line L10 (371.4666, 52.9827) -> (390.4666, 52.9827)
  line L11 (369.4666, 52.9827) -> (390.4666, 52.9827)
  line L12 (369.4664, 59.8721) -> (369.3896, 37.8723)
  line L13 (390.4666, 52.9827) -> (390.4666, 44.9827)
  line L14 (363.9178, 46.3914) -> (358.0535, 46.4059)
  line L15 (369.4664, 59.8721) -> (369.3896, 37.8723)
  line L16 (387.4666, 44.9827) -> (387.4666, 52.9827)
  line L17 (387.4666, 44.9827) -> (387.4666, 52.9827)
  line L18 (371.4666, 61.9827) -> (344.3915, 62.0013)
  line L19 (390.4666, 44.9827) -> (369.4666, 44.9827)
  line L20 (384.4666, 44.9827) -> (384.4666, 52.9827)
  line L21 (390.4666, 52.9827) -> (390.4666, 44.9827)
  line L22 (332.4666, 60.0013) -> (332.4666, 62.0013)
  line L23 (363.9073, 43.3914) -> (358.0433, 43.4179)
  line L24 (369.4664, 59.8721) -> (332.4666, 60.0013)
  line L25 (369.3896, 37.8723) -> (332.3898, 38.0014)
  line L26 (343.9473, 54.4612) -> (337.9474, 54.4821)
  line L27 (369.4664, 59.8721) -> (343.4665, 59.9629)
  line L28 (371.4666, 44.9827) -> (371.4666, 52.9827)
  line L29 (344.3895, 35.9861) -> (371.4666, 35.9841)
  line L30 (369.4666, 62.0013) -> (332.4666, 62.0013)
  line L31 (343.9361, 51.4612) -> (338.0323, 51.4848)
  line L32 (369.3896, 37.8723) -> (332.3898, 38.0014)
  line L33 (369.4664, 59.8721) -> (332.4666, 60.0013)
  line L34 (343.909, 43.4612) -> (337.909, 43.4822)
  line L35 (337.92, 46.4822) -> (344.0004, 46.4588)
  line L36 (369.4666, 44.9827) -> (369.4666, 52.9827)
  line L37 (369.4664, 59.8721) -> (332.4666, 60.0013)
  line L38 (369.3896, 37.8723) -> (332.3898, 38.0014)
  line L39 (332.4666, 60.0013) -> (332.3898, 38.0014)
  line L40 (343.3898, 37.963) -> (369.3896, 37.8723)
  line L41 (343.909, 43.4612) -> (337.909, 43.4822)
  line L42 (337.92, 46.4822) -> (343.8396, 46.4594)
  line L43 (363.9457, 54.3914) -> (358.0816, 54.4058)
  line L44 (369.4664, 59.8721) -> (369.3896, 37.8723)
  line L45 (332.4666, 35.9861) -> (369.4666, 35.9861)
  line L46 (369.4666, 62.0013) -> (332.4666, 62.0013)
  line L47 (332.4666, 60.0013) -> (332.3898, 38.0014)
  line L48 (332.4666, 62.0013) -> (332.4666, 35.9861)
  circle C1 centre (360.942, 52.9018) radius 1.5
  arc A1 centre (343.9142, 44.9612) radius 1.5 clockwise from (344.0004, 46.4588) to (343.909, 43.4612)
  circle C2 centre (360.9141, 44.9019) radius 1.5
  arc A2 centre (357.9141, 44.9124) radius 1.5 clockwise from (358.0433, 43.4179) to (358.0535, 46.4059)
  circle C3 centre (360.9141, 44.9019) radius 1.5
  arc A3 centre (363.9141, 44.8914) radius 1.5 clockwise from (363.9178, 46.3914) to (363.9073, 43.3914)
  circle C4 centre (364.4071, 42.8897) radius 2
  arc A4 centre (337.9421, 52.9821) radius 1.5 clockwise from (338.0323, 51.4848) to (337.9474, 54.4821)
  arc A5 centre (337.9142, 44.9822) radius 1.5 clockwise from (337.909, 43.4822) to (337.92, 46.4822)
  arc A6 centre (337.9142, 44.9822) radius 1.5 clockwise from (337.909, 43.4822) to (337.92, 46.4822)
  circle C5 centre (340.9142, 44.9717) radius 1.5
  circle C6 centre (340.9421, 52.9717) radius 1.5
  circle C7 centre (340.9142, 44.9717) radius 1.5
  arc A7 centre (337.9421, 52.9821) radius 1.5 clockwise from (338.0324, 51.4848) to (337.9474, 54.4821)
  arc A8 centre (357.9141, 44.9124) radius 1.5 clockwise from (358.0439, 43.418) to (358.0543, 46.4058)
  arc A9 centre (337.9421, 52.9821) radius 1.5 clockwise from (338.0324, 51.4848) to (337.9474, 54.4821)
  circle C8 centre (340.9421, 52.9717) radius 1.5
  arc A10 centre (337.9142, 44.9822) radius 1.5 clockwise from (337.909, 43.4822) to (337.92, 46.4822)
  circle C9 centre (340.9142, 44.9717) radius 1.5
  circle C10 centre (340.9421, 52.9717) radius 1.5
  arc A11 centre (363.942, 52.8914) radius 1.5 clockwise from (363.9457, 54.3914) to (363.9352, 51.3914)
  arc A12 centre (357.9141, 44.9124) radius 1.5 clockwise from (358.0439, 43.418) to (358.0543, 46.4058)
  arc A13 centre (357.942, 52.9123) radius 1.5 clockwise from (358.0718, 51.4179) to (358.0822, 54.4058)
  circle C11 centre (348.9491, 54.9437) radius 2
  circle C12 centre (360.942, 52.9018) radius 1.5
  arc A14 centre (343.9421, 52.9612) radius 1.5 clockwise from (343.9473, 54.4612) to (343.9361, 51.4612)
  circle C13 centre (360.9141, 44.9019) radius 1.5
  circle C14 centre (360.942, 52.9018) radius 1.5
  arc A15 centre (343.9142, 44.9612) radius 1.5 clockwise from (343.8396, 46.4594) to (343.909, 43.4612)
  arc A16 centre (357.942, 52.9123) radius 1.5 clockwise from (358.071, 51.4179) to (358.0816, 54.4058)
  arc A17 centre (357.942, 52.9123) radius 1.5 clockwise from (358.0718, 51.4179) to (358.0822, 54.4058)
  point P29 (390.4666, 44.9827)
  point P60 (390.4666, 44.9827)
  point P39 (390.4666, 52.9827)
  point P104 (390.4666, 52.9827)
  point P41 (390.4666, 44.9827)
  point P13 (387.4666, 52.9827)
  point P55 (387.4666, 52.9827)
  point P5 (387.4666, 44.9827)
  point P52 (387.4666, 44.9827)
  point P34 (384.4666, 52.9827)
  point P90 (384.4666, 52.9827)
  point P30 (384.4666, 44.9827)
  point P45 (384.4666, 44.9827)
  point P35 (344.3915, 62.0013)
  point P16 (343.3898, 37.963)
  point P22 (343.3898, 37.963)
  point P20 (343.3898, 37.963)
  point P108 (332.4666, 62.0013)
  point P125 (332.4666, 60.0013)
  coincident P29 P60
  coincident P39 P104
  perpendicular L10 L21
  perpendicular L11 L28
  coincident P29 P41
  perpendicular L4 L28
  coincident P13 P55
  coincident P5 P52
  coincident P34 P90
  coincident P30 P45
  coincident P35 L30
  perpendicular L6 L29
  coincident P16 P22
  perpendicular L3 L27
  perpendicular L9 L27
  coincident P16 P20
  perpendicular L3 L40
  perpendicular L22 L46
  dimension "d70" distance P108 P125 = 2
  dimension "d915" diameter C4 = 4
sketch "Sketch10" plane through (0, 0, 0) normal (0, 0, 1) x axis (1, 0, 0)
extrude "Extrude2" new body sketch "Bottom Runways" along normal blind 3 bodies "Left Lower Deck Section"
extrude "Extrude3" add sketch "Bottom Runways" along normal blind 25
extrude "Extrude4" new body sketch "Bottom Runways" profile of L83 L48 L49 along normal blind 25 bodies "Middle Lower Deck Section"
extrude "Extrude5" add sketch "Bottom Runways" profile of L45 L83 along normal blind 25
extrude "Extrude6" add sketch "Bottom Runways" along normal blind 3
extrude "Extrude7" add sketch "Bottom Runways" along normal blind 25
extrude "Extrude8" new body sketch "Bottom Runways" along normal blind 3 bodies "Right Lower Deck Section"
extrude "Extrude9" new body sketch "Bottom Runways" along normal blind 25
extrude "Extrude10" add sketch "Bottom Runways" profile of L83 L56 L59 L60 L62 L63 L92 L90 along normal blind 3
extrude "Extrude11" add sketch "Bottom Runways" along normal blind 25
extrude "Extrude12" add sketch "Bottom Runways" profile of L83 L12 L17 L40 along normal blind 25
extrude "Extrude13" add sketch "Bottom Runways" along normal blind 25
extrude "Extrude15" add sketch "Bottom Runways" along normal blind 17
extrude "Extrude16" add sketch "Launch_reload_Plunger" profile of L1 C1 A1 C2 L3 L6 L7 L8 L9 L12 L14 L15 L18 A2 C3 A3 C4 A4 A5 A6 C5 C6 C7 A7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 along normal blind 8
extrude "Extrude17" cut sketch "Launch_reload_Plunger" profile of C1 A1 C2 L3 L6 L8 L14 A2 C3 A3 C4 A4 A5 A6 C5 C6 C7 A7 A8 A9 C8 A10 C9 C10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 along normal blind 10
extrude "Extrude18" cut sketch "Bottom Runways" along normal blind 4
